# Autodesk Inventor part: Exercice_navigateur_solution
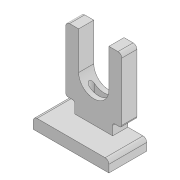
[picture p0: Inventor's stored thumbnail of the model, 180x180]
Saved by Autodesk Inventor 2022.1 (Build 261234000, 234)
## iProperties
Created: 2021-03
Part Number: Exercice_navigateur_solution
Material: Générique
Document SubType Name: Modeling
Designer: Fabian
Mass: 152.41 g
Surface Area: 332.904 cm^2
Volume: 152.41 cm^3
Density: 1 g/cm^3
Appearance: Par défaut
Author: Fabian
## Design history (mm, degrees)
sketch "Esquisse1"
  geometry: L1 (-20, 0)-(-20, 50); L2 (-20, 50)-(-37, 50); L3 (-37, 50)-(-37, -35); L4 (-37, -35)-(-25, -35); L5 (-25, -35)-(-25, -50); L6 (-25, -50)-(-50, -50); L7 (-50, -50)-(-50, -65); L8 (-50, -65)-(0, -65); L9 (0, 50)-(0, -65); L10 (-25, -50)-(0, -50); A1 r 20 centre (0, 0) between (-20, 0) and (0, -20); 2 further points
  constraints: 21 end point, 6 perpendicular, 4 point on line, 3 vertical, 2 point on circle, 1 centre point, 1 coincident, 1 horizontal, 1 midpoint, 1 tangent
  dimensions: "d0" = 40 diameter of A1; "d1" = 74 diameter of L3 L9; "d2" = 115 distance between parallel lines of L8 L2; "d3" = 30 distance between parallel lines of L8 L4; "d4" = 15 distance of L6.end L7.end; "d5" = 100 diameter of L7 L9; "d6" = 50 diameter of L5 L9; "d7" = 65 distance from line of L8 point (0, 0)
extrude "Extrusion1" new body sketch "Esquisse1" distance "d8" = 20; taper "d9" = 0 deg
extrude "Extrusion3" join sketch "Esquisse1" distance "d22" = 50; taper "d23" = 0 deg
fillet "Congé2" dims "d24" = 5, "d25" = 3
mirror "Symétrie2"
sketch "Esquisse3"
  geometry: L1 (12.5, 10)-(37.5, 10); L2 (12.5, 6.5)-(37.5, 6.5); L3 (37.5, 13.5)-(12.5, 13.5); L4 (25, 0)-(25, 20) reference; A1 r 3.5 centre (12.5, 10) between (12.5, 13.5) and (12.5, 6.5); A2 r 3.5 centre (37.5, 10) between (37.5, 6.5) and (37.5, 13.5); 2 further points
  constraints: 8 end point, 4 point on circle, 4 tangent, 2 centre point, 2 midpoint, 1 coincident, 1 horizontal, 1 parallel
  dimensions: "d26" = 7 diameter of A2; "d27" = 25 distance of L1.start L1.end
extrude "Extrusion4" cut sketch "Esquisse3" extent not by distance; stored distance "d28" = 0; taper "d29" = 0 deg
node "Solide1"
